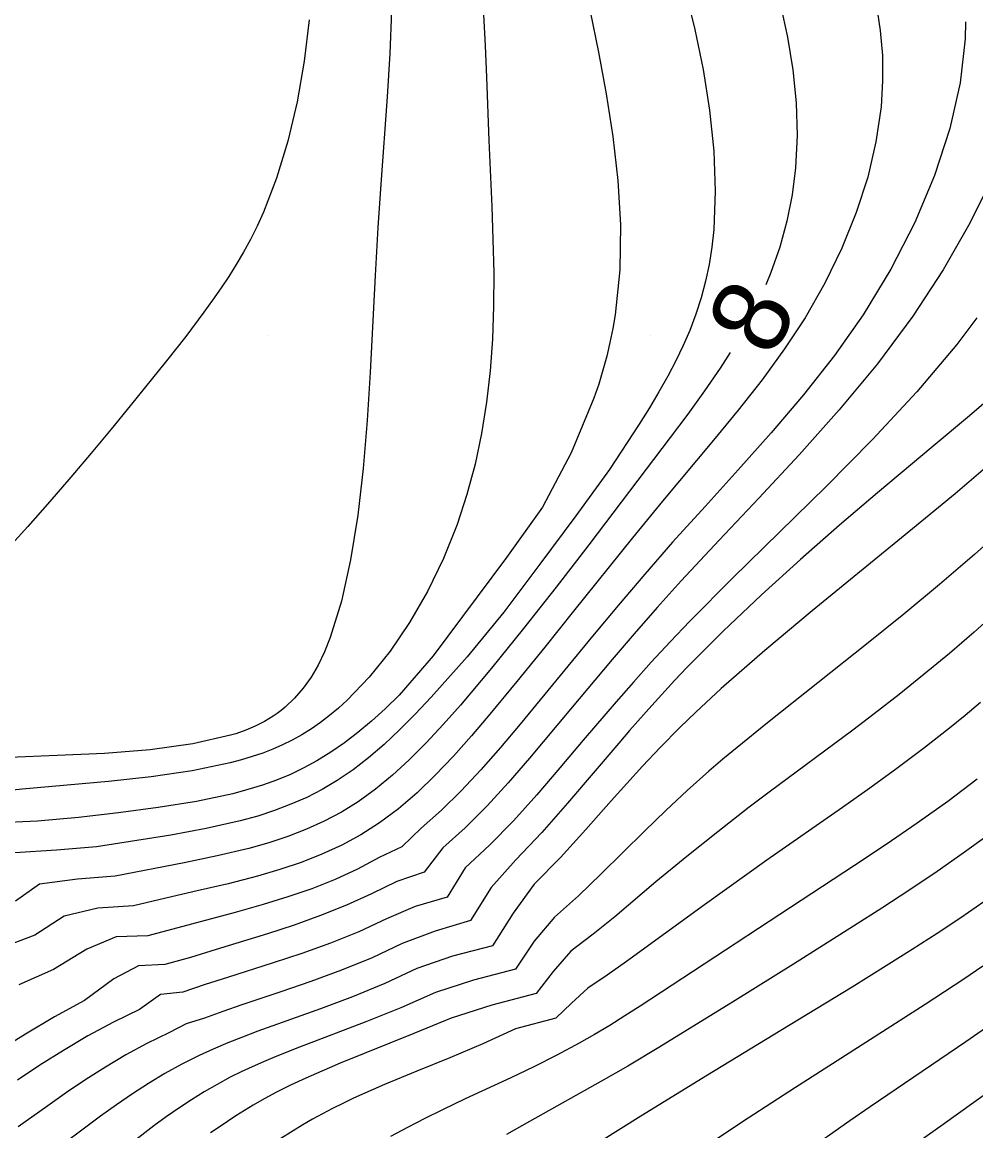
# Model space of a CAD drawing. Extents: x 2602990 to 2605851, y 618069 to 619180.
# Drawn here: x 2603263.62 to 2603288.47, y 618499.28 to 618528.17 of the extents above; entities that cross this region are included whole.
import ezdxf

# ---------------------------------------------------------------- set-up
doc = ezdxf.new("R2010")
doc.units = 0
for name, color, linetype in [('DTM Contours Major', 7, 'Continuous'), ('DTM Contours Major Text', 7, 'Continuous'), ('DTM Contours Minor', 7, 'Continuous'), ('Exist DTM Crownline', 7, 'Continuous'), ('Exist DTM QL2 LIDAR Elevation Point', 7, 'Continuous'), ('Exist Roads EOP', 7, 'Continuous')]:
    doc.layers.add(name, color=color, linetype=linetype)

msp = doc.modelspace()

# ---------------------------------------------------------------- linework, layer by layer
at = {"layer": 'DTM Contours Major'}
for points in [[(2603283.378, 618528.616), (2603283.562, 618527.781), (2603283.699, 618526.931), (2603283.783, 618526.075), (2603283.808, 618525.22), (2603283.769, 618524.375), (2603283.682, 618523.677), (2603283.546, 618522.99), (2603283.361, 618522.315), (2603283.129, 618521.649), (2603282.994, 618521.332)], [(2603282.065, 618519.564), (2603281.808, 618519.161), (2603281.401, 618518.566), (2603280.965, 618517.964), (2603280.506, 618517.348), (2603278.385, 618514.558), (2603277.535, 618513.456), (2603276.684, 618512.375), (2603275.845, 618511.341), (2603275.034, 618510.381), (2603274.583, 618509.871), (2603274.142, 618509.396), (2603273.704, 618508.956), (2603273.266, 618508.553), (2603272.824, 618508.188), (2603272.372, 618507.861), (2603271.935, 618507.591), (2603271.486, 618507.352), (2603271.021, 618507.142), (2603270.539, 618506.956), (2603270.04, 618506.792), (2603269.523, 618506.645), (2603268.699, 618506.447), (2603267.838, 618506.268), (2603266.043, 618505.919), (2603265.054, 618505.841), (2603264.071, 618505.713), (2603263.443, 618505.268)], [(2603288.502, 618508.448), (2603287.736, 618507.87), (2603286.941, 618507.302), (2603286.128, 618506.744), (2603285.305, 618506.195), (2603279.719, 618502.533), (2603279.323, 618502.279), (2603278.929, 618502.032), (2603278.533, 618501.794), (2603278.134, 618501.566), (2603277.548, 618501.253), (2603276.953, 618500.956), (2603276.353, 618500.67), (2603275.159, 618500.115), (2603274.573, 618499.836), (2603274.113, 618499.608), (2603273.66, 618499.374), (2603273.215, 618499.134)]]:
    msp.add_lwpolyline(points, dxfattribs=at)
at = {"layer": 'DTM Contours Minor'}
for points in [[(2603280.902, 618528.976), (2603281.148, 618527.981), (2603281.36, 618526.941), (2603281.527, 618525.88), (2603281.637, 618524.816), (2603281.679, 618523.773), (2603281.641, 618522.771), (2603281.591, 618522.311), (2603281.52, 618521.863), (2603281.427, 618521.424), (2603281.311, 618520.993), (2603281.173, 618520.567), (2603281.011, 618520.143), (2603280.84, 618519.75), (2603280.649, 618519.354), (2603280.438, 618518.953), (2603280.209, 618518.546), (2603279.96, 618518.129), (2603279.694, 618517.7), (2603278.919, 618516.519), (2603278.043, 618515.308), (2603277.106, 618514.048), (2603276.17, 618512.8), (2603275.209, 618511.638), (2603274.277, 618510.585), (2603273.859, 618510.142), (2603273.449, 618509.731), (2603273.045, 618509.353), (2603272.643, 618509.007), (2603272.238, 618508.695), (2603271.828, 618508.415), (2603271.436, 618508.182), (2603271.034, 618507.975), (2603270.62, 618507.793), (2603270.194, 618507.631), (2603269.753, 618507.488), (2603269.295, 618507.361), (2603268.414, 618507.16), (2603267.487, 618506.99), (2603265.554, 618506.683), (2603264.514, 618506.597), (2603263.421, 618506.532)], [(2603278.415, 618528.453), (2603278.631, 618527.393), (2603278.833, 618526.31), (2603279.009, 618525.194), (2603279.14, 618524.052), (2603279.207, 618522.892), (2603279.19, 618521.722), (2603279.068, 618520.551), (2603279.007, 618520.19), (2603278.933, 618519.829), (2603278.848, 618519.468), (2603278.75, 618519.106), (2603278.639, 618518.743), (2603278.516, 618518.378), (2603277.922, 618516.954), (2603277.173, 618515.535), (2603276.237, 618514.223), (2603274.323, 618511.66), (2603273.437, 618510.636), (2603273.076, 618510.285), (2603272.72, 618509.962), (2603272.367, 618509.665), (2603272.013, 618509.394), (2603271.658, 618509.148), (2603271.298, 618508.926), (2603270.955, 618508.74), (2603270.605, 618508.574), (2603270.247, 618508.426), (2603269.879, 618508.293), (2603269.5, 618508.176), (2603269.108, 618508.07), (2603268.16, 618507.868), (2603267.16, 618507.709), (2603266.126, 618507.575), (2603265.08, 618507.452), (2603264.014, 618507.35), (2603262.865, 618507.299)], [(2603285.882, 618528.603), (2603285.979, 618527.958), (2603286.032, 618527.304), (2603286.038, 618526.642), (2603285.997, 618525.968), (2603285.865, 618525.06), (2603285.649, 618524.138), (2603285.352, 618523.212), (2603284.979, 618522.287), (2603284.532, 618521.372), (2603284.016, 618520.474), (2603283.48, 618519.659), (2603282.897, 618518.859), (2603282.278, 618518.068), (2603281.633, 618517.281), (2603280.301, 618515.69), (2603279.52, 618514.737), (2603277.984, 618512.824), (2603277.237, 618511.89), (2603276.51, 618510.991), (2603275.805, 618510.139), (2603275.324, 618509.576), (2603274.852, 618509.045), (2603274.381, 618508.551), (2603273.907, 618508.094), (2603273.424, 618507.679), (2603272.927, 618507.308), (2603272.443, 618507.001), (2603271.942, 618506.731), (2603271.423, 618506.492), (2603270.885, 618506.281), (2603270.328, 618506.093), (2603269.751, 618505.923), (2603268.98, 618505.724), (2603268.18, 618505.536), (2603267.358, 618505.349), (2603266.518, 618505.15), (2603265.588, 618505.09), (2603264.712, 618504.882), (2603263.944, 618504.38), (2603263.075, 618504.052)], [(2603273.238, 618528.47), (2603273.198, 618527.358), (2603273.131, 618526.231), (2603272.963, 618523.956), (2603272.885, 618522.821), (2603272.815, 618521.57), (2603272.687, 618519.042), (2603272.606, 618517.796), (2603272.5, 618516.547), (2603272.359, 618515.325), (2603272.175, 618514.163), (2603271.94, 618513.091), (2603271.646, 618512.141), (2603271.494, 618511.766), (2603271.327, 618511.42), (2603271.143, 618511.104), (2603270.94, 618510.816), (2603270.716, 618510.556), (2603270.47, 618510.324), (2603270.369, 618510.242), (2603270.264, 618510.164), (2603270.156, 618510.09), (2603270.043, 618510.019), (2603269.927, 618509.952), (2603269.689, 618509.832), (2603269.442, 618509.728), (2603269.181, 618509.634), (2603269.044, 618509.591), (2603268.063, 618509.365), (2603266.955, 618509.215), (2603265.761, 618509.121), (2603264.523, 618509.062), (2603263.284, 618509.016)], [(2603275.638, 618528.374), (2603275.683, 618527.561), (2603275.717, 618526.743), (2603275.777, 618525.094), (2603275.853, 618523.375), (2603275.884, 618522.511), (2603275.903, 618521.645), (2603275.901, 618520.778), (2603275.871, 618519.913), (2603275.811, 618519.089), (2603275.717, 618518.27), (2603275.586, 618517.457), (2603275.417, 618516.654), (2603275.206, 618515.864), (2603274.951, 618515.088), (2603274.593, 618514.196), (2603274.177, 618513.341), (2603273.711, 618512.532), (2603273.202, 618511.782), (2603272.657, 618511.103), (2603272.084, 618510.504), (2603271.858, 618510.298), (2603271.628, 618510.106), (2603271.393, 618509.926), (2603271.152, 618509.76), (2603270.905, 618509.606), (2603270.649, 618509.464), (2603270.402, 618509.343), (2603270.147, 618509.231), (2603269.884, 618509.128), (2603269.611, 618509.035), (2603269.329, 618508.949), (2603269.037, 618508.871), (2603268.047, 618508.665), (2603266.98, 618508.51), (2603265.867, 618508.391), (2603263.618, 618508.19), (2603262.541, 618508.076)], [(2603271.093, 618528.234), (2603270.966, 618527.159), (2603270.78, 618526.099), (2603270.54, 618525.076), (2603270.247, 618524.109), (2603269.906, 618523.22), (2603269.74, 618522.857), (2603269.567, 618522.512), (2603269.385, 618522.18), (2603269.196, 618521.861), (2603269.001, 618521.551), (2603268.8, 618521.248), (2603268.579, 618520.93), (2603268.351, 618520.616), (2603267.876, 618519.988), (2603267.373, 618519.348), (2603266.432, 618518.177), (2603265.932, 618517.568), (2603265.415, 618516.947), (2603264.883, 618516.319), (2603264.338, 618515.688), (2603263.759, 618515.033), (2603263.168, 618514.384)], [(2603288.198, 618528.187), (2603288.187, 618527.737), (2603288.057, 618526.593), (2603287.789, 618525.402), (2603287.393, 618524.182), (2603286.878, 618522.954), (2603286.255, 618521.737), (2603285.533, 618520.55), (2603284.785, 618519.49), (2603283.979, 618518.466), (2603283.136, 618517.474), (2603282.273, 618516.506), (2603281.41, 618515.558), (2603280.567, 618514.623), (2603279.842, 618513.794), (2603279.145, 618512.976), (2603278.474, 618512.171), (2603276.59, 618509.886), (2603276.077, 618509.276), (2603275.569, 618508.696), (2603275.059, 618508.148), (2603274.542, 618507.639), (2603274.011, 618507.172), (2603273.507, 618506.684), (2603272.919, 618506.409), (2603272.355, 618506.104), (2603271.769, 618505.835), (2603271.163, 618505.595), (2603270.538, 618505.379), (2603269.894, 618505.181), (2603269.165, 618504.977), (2603266.887, 618504.369), (2603266.064, 618504.338), (2603265.298, 618504.019), (2603264.43, 618503.488), (2603263.526, 618503.087)], [(2603288.913, 618524.144), (2603288.311, 618522.941), (2603287.615, 618521.723), (2603286.826, 618520.514), (2603285.901, 618519.273), (2603284.903, 618518.069), (2603283.862, 618516.902), (2603282.81, 618515.772), (2603281.776, 618514.677), (2603280.789, 618513.618), (2603280.159, 618512.919), (2603279.56, 618512.236), (2603278.988, 618511.568), (2603277.907, 618510.277), (2603276.835, 618508.993), (2603276.284, 618508.356), (2603275.729, 618507.751), (2603275.162, 618507.183), (2603274.574, 618506.661), (2603274.092, 618506.023), (2603273.376, 618505.778), (2603272.722, 618505.464), (2603272.067, 618505.162), (2603271.393, 618504.892), (2603270.705, 618504.647), (2603270.006, 618504.419), (2603268.672, 618504.012), (2603268.004, 618503.804), (2603267.335, 618503.616), (2603266.645, 618503.586), (2603266.008, 618503.246), (2603265.236, 618502.683), (2603264.459, 618502.255), (2603263.705, 618501.807), (2603262.272, 618500.921)], [(2603288.498, 618520.472), (2603287.971, 618519.777), (2603286.927, 618518.54), (2603285.777, 618517.303), (2603284.565, 618516.077), (2603282.138, 618513.697), (2603281.013, 618512.563), (2603280.5, 618512.024), (2603280.011, 618511.496), (2603279.544, 618510.977), (2603279.095, 618510.466), (2603278.235, 618509.461), (2603277.627, 618508.741), (2603277.024, 618508.039), (2603276.416, 618507.365), (2603275.796, 618506.731), (2603275.16, 618506.138), (2603274.687, 618505.377), (2603273.857, 618505.128), (2603273.109, 618504.807), (2603272.388, 618504.473), (2603271.651, 618504.176), (2603270.904, 618503.908), (2603270.156, 618503.66), (2603268.967, 618503.284), (2603268.381, 618503.094), (2603267.802, 618502.896), (2603267.221, 618502.837), (2603266.677, 618502.449), (2603265.992, 618502.12), (2603265.329, 618501.761), (2603264.691, 618501.382), (2603264.079, 618500.994), (2603263.495, 618500.607)], [(2603288.736, 618518.289), (2603288.306, 618517.916), (2603287.357, 618517.122), (2603285.907, 618515.913), (2603284.919, 618515.069), (2603283.901, 618514.177), (2603282.88, 618513.251), (2603281.882, 618512.305), (2603280.934, 618511.355), (2603280.622, 618511.026), (2603280.02, 618510.371), (2603279.442, 618509.717), (2603279.16, 618509.389), (2603277.828, 618507.819), (2603277.159, 618507.062), (2603276.476, 618506.344), (2603275.833, 618505.626), (2603275.3, 618504.764), (2603274.374, 618504.49), (2603273.519, 618504.168), (2603272.732, 618503.797), (2603271.935, 618503.469), (2603271.14, 618503.175), (2603270.356, 618502.905), (2603269.34, 618502.565), (2603268.847, 618502.395), (2603268.365, 618502.22), (2603267.887, 618502.074), (2603267.433, 618501.836), (2603266.867, 618501.561), (2603266.318, 618501.263), (2603265.786, 618500.947), (2603265.27, 618500.618), (2603264.769, 618500.281), (2603264.283, 618499.94), (2603263.511, 618499.389)], [(2603289.022, 618516.819), (2603287.925, 618515.883), (2603286.724, 618514.892), (2603284.2, 618512.832), (2603282.973, 618511.805), (2603281.832, 618510.807), (2603281.171, 618510.196), (2603280.755, 618509.795), (2603280.238, 618509.273), (2603279.779, 618508.787), (2603278.964, 618507.884), (2603278.306, 618507.141), (2603277.643, 618506.41), (2603276.961, 618505.71), (2603276.41, 618504.959), (2603275.869, 618504.108), (2603274.833, 618503.836), (2603273.9, 618503.511), (2603273.064, 618503.121), (2603272.221, 618502.776), (2603271.389, 618502.464), (2603269.755, 618501.878), (2603269.358, 618501.729), (2603268.971, 618501.576), (2603268.595, 618501.417), (2603268.228, 618501.25), (2603267.776, 618501.022), (2603267.337, 618500.779), (2603266.908, 618500.52), (2603266.487, 618500.248), (2603266.072, 618499.963), (2603265.66, 618499.668), (2603264.239, 618498.608)], [(2603289.306, 618515.082), (2603288.436, 618514.305), (2603287.524, 618513.524), (2603286.591, 618512.752), (2603285.658, 618511.997), (2603283.035, 618509.913), (2603282.251, 618509.277), (2603281.877, 618508.966), (2603281.514, 618508.655), (2603280.946, 618508.151), (2603280.39, 618507.634), (2603279.833, 618507.095), (2603278.708, 618505.978), (2603278.113, 618505.41), (2603277.487, 618504.853), (2603276.955, 618504.226), (2603276.473, 618503.495), (2603275.38, 618503.209), (2603274.388, 618502.886), (2603273.481, 618502.489), (2603272.574, 618502.126), (2603270.845, 618501.468), (2603270.209, 618501.214), (2603269.905, 618501.086), (2603269.609, 618500.955), (2603269.321, 618500.821), (2603269.04, 618500.681), (2603268.694, 618500.496), (2603268.356, 618500.301), (2603268.025, 618500.095), (2603267.697, 618499.879), (2603267.372, 618499.652), (2603267.046, 618499.414), (2603266.495, 618498.993)], [(2603289.062, 618512.855), (2603288.425, 618512.28), (2603287.778, 618511.722), (2603287.125, 618511.181), (2603286.471, 618510.657), (2603285.82, 618510.15), (2603285.259, 618509.725), (2603283.083, 618508.109), (2603282.561, 618507.715), (2603281.741, 618507.08), (2603280.936, 618506.435), (2603280.132, 618505.769), (2603279.057, 618504.864), (2603278.497, 618504.411), (2603277.913, 618503.967), (2603277.454, 618503.436), (2603277.012, 618502.862), (2603275.854, 618502.555), (2603274.799, 618502.224), (2603273.826, 618501.818), (2603271.905, 618501.048), (2603271.004, 618500.661), (2603270.609, 618500.475), (2603270.228, 618500.284), (2603269.859, 618500.085), (2603269.631, 618499.953), (2603269.406, 618499.818), (2603269.184, 618499.678), (2603268.745, 618499.383), (2603268.527, 618499.229)], [(2603288.592, 618510.449), (2603288.191, 618510.109), (2603287.782, 618509.775), (2603287.105, 618509.246), (2603286.41, 618508.726), (2603285.704, 618508.215), (2603284.992, 618507.711), (2603283.021, 618506.334), (2603281.396, 618505.177), (2603279.36, 618503.693), (2603278.863, 618503.342), (2603278.355, 618503.001), (2603277.935, 618502.614), (2603277.522, 618502.22), (2603276.473, 618501.942), (2603275.623, 618501.556), (2603274.758, 618501.191), (2603273.896, 618500.838), (2603273.054, 618500.488), (2603272.251, 618500.132), (2603271.975, 618500), (2603271.705, 618499.866), (2603271.44, 618499.728), (2603271.181, 618499.586), (2603270.926, 618499.439), (2603270.674, 618499.287), (2603270.286, 618499.038)], [(2603288.785, 618506.99), (2603288.138, 618506.519), (2603287.457, 618506.045), (2603286.749, 618505.568), (2603286.021, 618505.091), (2603285.279, 618504.614), (2603283.72, 618503.627), (2603282.195, 618502.679), (2603280.205, 618501.458), (2603279.396, 618500.974), (2603278.752, 618500.602), (2603276.833, 618499.532), (2603276.239, 618499.192)], [(2603288.675, 618505.248), (2603288.079, 618504.839), (2603287.456, 618504.425), (2603286.807, 618504.007), (2603286.133, 618503.583), (2603285.245, 618503.032), (2603283.388, 618501.9), (2603281.473, 618500.737), (2603279.736, 618499.667), (2603276.011, 618497.33)], [(2603288.648, 618503.575), (2603288.157, 618503.241), (2603287.148, 618502.577), (2603285.817, 618501.724), (2603283.767, 618500.418), (2603282.531, 618499.613), (2603279.751, 618497.767)], [(2603288.947, 618502.113), (2603288.208, 618501.602), (2603285.718, 618499.912), (2603285.186, 618499.545), (2603282.77, 618497.847)], [(2603289.276, 618500.638), (2603287.619, 618499.453), (2603285.145, 618497.696)]]:
    msp.add_lwpolyline(points, dxfattribs=at)
at = {"layer": 'Exist DTM Crownline'}
msp.add_spline([(2603233.488, 618380.754), (2603285.185, 618400.095), (2603335.457, 618418.629), (2603390.812, 618439.069), (2603440.087, 618457.325), (2603493.996, 618477.231), (2603542.655, 618495.301), (2603600.808, 618516.867), (2603653.659, 618536.362), (2603706.222, 618555.742), (2603764.811, 618577.593), (2603823.52, 618599.847), (2603878.564, 618620.56), (2603937.951, 618643.078), (2603997.369, 618665.789), (2604036.209, 618680.665), (2604055.311, 618688.017)], degree=3, dxfattribs=at)
at = {"layer": 'Exist DTM QL2 LIDAR Elevation Point'}
for p, q in [((2603270, 618520), (2603270, 618520)), ((2603280, 618520), (2603280, 618520)), ((2603270, 618510), (2603270, 618510)), ((2603280, 618510), (2603280, 618510)), ((2603270, 618500), (2603270, 618500)), ((2603280, 618500), (2603280, 618500))]:
    msp.add_line(p, q, dxfattribs=at)
at = {"layer": 'Exist Roads EOP'}
for points in [[(2603230.17, 618389.98), (2603282.929, 618409.597), (2603332.773, 618427.868), (2603388.167, 618448.413), (2603437.203, 618466.721), (2603490.778, 618486.527), (2603539.039, 618504.558), (2603597.451, 618526.156), (2603651.053, 618545.972), (2603705.208, 618566.084), (2603762.02, 618587.183), (2603820.334, 618609.162), (2603876.341, 618629.99), (2603934.909, 618652.28), (2603996.409, 618675.568), (2604033.216, 618689.957), (2604052.01, 618697.199)], [(2604034.633, 618668.486), (2603984.89, 618650.123), (2603936.767, 618631.654), (2603888.195, 618613.335), (2603837.766, 618594.258), (2603782.918, 618573.705), (2603731.939, 618554.39), (2603671.126, 618532.171), (2603621.822, 618514.106), (2603561.545, 618491.877), (2603506.421, 618471.293), (2603452.163, 618451.33), (2603398.364, 618431.316), (2603341.431, 618410.355), (2603281.65, 618388.199), (2603223.033, 618366.475), (2603185.717, 618352.612)]]:
    msp.add_spline(points, degree=3, dxfattribs=at)

# ---------------------------------------------------------------- texts
at = {"layer": 'DTM Contours Major Text'}
msp.add_text('8', height=2, rotation=62.2626, dxfattribs=at).set_placement((2603283.148, 618519.385))

doc.saveas('drawing.dxf')
